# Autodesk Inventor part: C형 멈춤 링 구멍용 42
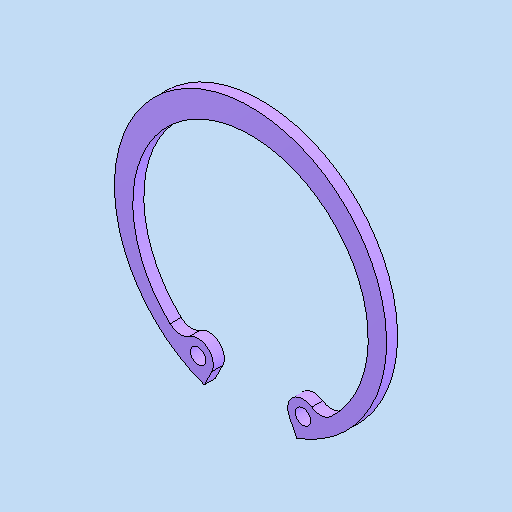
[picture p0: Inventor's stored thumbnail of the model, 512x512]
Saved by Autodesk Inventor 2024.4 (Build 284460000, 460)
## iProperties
Created: 2025-11
Part Number: C형 멈춤 링 구멍용 42
Material: 강철, 연강
Description: 리테이닝 링(C형)
Document SubType Name: Modeling
Designer: home
Density: 7.85 g/cm^3
Appearance: 기본값
Sending System: Autodesk Inventor 2026
Preprocessor: ST-DEVELOPER v20.1
Author: jhkim
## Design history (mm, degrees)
feature "Solid1"
node "솔리드1"
